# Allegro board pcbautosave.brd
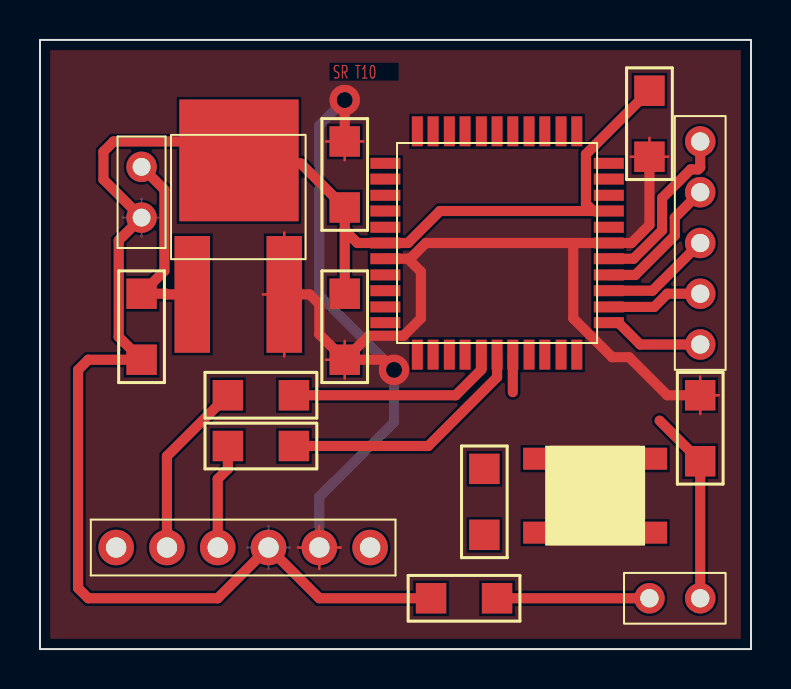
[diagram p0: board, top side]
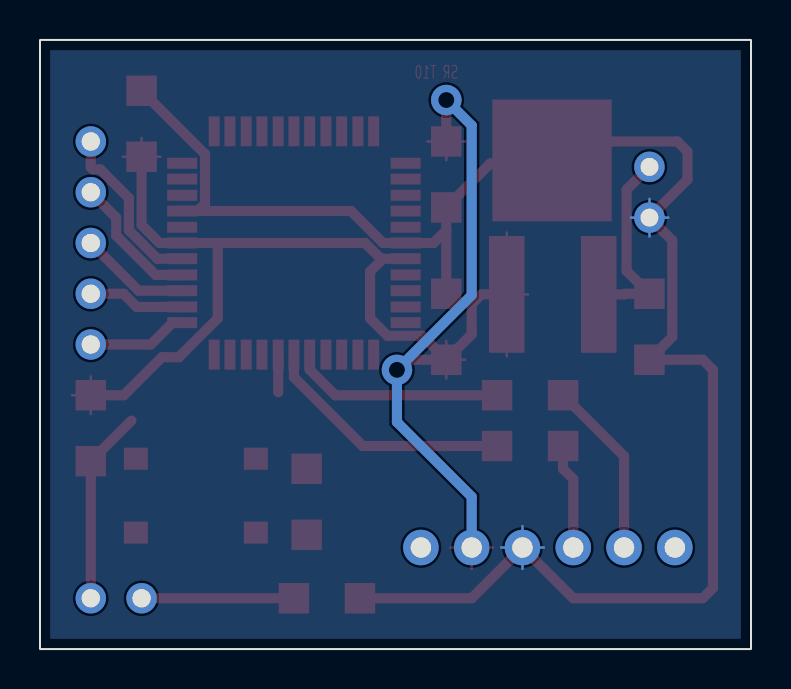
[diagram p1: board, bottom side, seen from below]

Outline 35.56 x 30.48 mm; copper layers: TOP, BOTTOM. Coordinates in mm from the lower left corner of the outline.
Outline path: rectangle 0,0 35.56,30.48

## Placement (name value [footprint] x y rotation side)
BT1  7.2V  [HEADER2]  5.08 22.86 0 top
C1  0.1uF, 15V  [SMC1206]  5.08 17.78 270 top
C2  0.1uF, 15V  [SMC1206]  15.24 25.4 270 top
C3  0.1uF, 15V  [SMC1206]  30.48 27.94 270 top
C4  0.1 uF, 15V  [SMC1206]  22.86 2.54 180 top
C5  0.1uF, 15V  [SMC1206]  15.24 17.78 270 top
J1  JUMPER  [JUMPER2]  30.48 2.54 0 top
J2  CON6  [HEADER6]  10.16 5.08 270 top
J3  HEADER 5  [JUMPER5]  33.02 15.24 90 top
R1  10 kohm, 1/4W  [SMR1206]  33.02 12.7 270 top
R2  220 ohm, 1/4W  [SMR1206]  22.22 5.72 90 top
R3  22 ohm, 1/4W  [SMR1206]  12.7 12.7 180 top
R4  22 ohm, 1/4W  [SMR1206]  12.7 10.16 180 top
SW1  SW PUSHBUTTON-SPST-2  [SMDSWITCH]  24.76 9.53 0 top
U1  LD29150DT33R  [TO252AA]  7.62 17.78 0 top
U2  PIC18F47K40-I/PT  [TQFPPIC18F47K40]  22.86 20.32 0 top

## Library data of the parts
BT1 = BATTERY
C1-C5 = CAP NP
J1 = JUMPER: User Part Number: ***
J2 = CON6
J3 = HEADER 5: User Part Number: ***
R1-R4 = R
SW1 = SW PUSHBUTTON-SPST-2
U1 = LD29150DT33R
U2 = PIC18F47K40-I/PT_2

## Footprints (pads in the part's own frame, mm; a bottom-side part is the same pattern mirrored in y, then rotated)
HEADER2
  round 1.524 hole 0.889: 1(0,1.27) 2(0,-1.27)
HEADER6
  round 1.778 hole 1.016: 1(0,6.35) 2(0,3.81) 3(0,1.27) 4(0,-1.27) 5(0,-3.81) 6(0,-6.35)
JUMPER2
  round 1.524 hole 0.914: 1(0,0) 2(2.54,0)
JUMPER5
  round 1.524 hole 0.914: 1(0,0) 2(2.54,0) 3(5.08,0) 4(7.62,0) 5(10.16,0)
SMC1206
  rect 1.524x1.524 smd: 1(0,0) 2(3.302,0)
SMDSWITCH
  rect 1.2x1.1 smd: 1(0,0) 2(6,0) 3(0,-3.7) 4(6,-3.7)
SMR1206
  rect 1.524x1.524 smd: 1(0,0) 2(3.302,0)
TO252AA
  rect 1.778x5.842 smd: 1(-0.004,-0.034) 3(4.596,-0.034)
  rect 5.969x6.096 smd: 2(2.332,6.673)
TQFPPIC18F47K40
  rect 1.5x0.55 smd: 1(-5.588,3.988) 2(-5.588,3.2) 3(-5.588,2.388) 4(-5.588,1.6) 5(-5.588,0.787) 6(-5.588,0) 7(-5.588,-0.787) 8(-5.588,-1.6) 9(-5.588,-2.388) 10(-5.588,-3.2) 11(-5.588,-3.988) 23(5.588,-3.988) 24(5.588,-3.2) 25(5.588,-2.388) 26(5.588,-1.6) 27(5.588,-0.787) 28(5.588,0) 29(5.588,0.787) 30(5.588,1.6) 31(5.588,2.388) 32(5.588,3.2) 33(5.588,3.988)
  rect 0.55x1.5 smd: 12(-3.988,-5.588) 13(-3.2,-5.588) 14(-2.388,-5.588) 15(-1.6,-5.588) 16(-0.787,-5.588) 17(0,-5.588) 18(0.787,-5.588) 19(1.6,-5.588) 20(2.388,-5.588) 21(3.2,-5.588) 22(3.988,-5.588) 34(3.988,5.588) 35(3.2,5.588) 36(2.388,5.588) 37(1.6,5.588) 38(0.787,5.588) 39(0,5.588) 40(-0.787,5.588) 41(-1.6,5.588) 42(-2.388,5.588) 43(-3.2,5.588) 44(-3.988,5.588)

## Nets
3.3V: C2.1 C3.2 C5.2 J2.2 R1.1 U1.3(OUT) U2.7(VDD_0) U2.28(VDD_1)
GND: BT1.2(-) C1.2 C2.2 C3.1 C4.2 C5.1 J2.3 SW1.3 U1.2(GND) U2.6(VSS_0) U2.30(VSS_1)
ICSPCLK: R3.1 U2.16(ICSPCLK/RB6)
ICSPDAT: R4.1 U2.17(ICSPDAT/RB7)
MCLR/VPP: J2.1 R2.1 U2.18(VPP/MCLR/RE3)
N103726: BT1.1(+) C1.1 U1.1(IN)
N112049: J2.4 R4.2
N112053: J2.5 R3.2
N112388: J1.2 R1.2 R2.2 SW1.1
N112486: C4.1 J1.1
N115043: J3.1 U2.23(RA4)
N115055: J3.2 U2.24(RA5)
N115065: J3.3 U2.25(RE0)
N115078: J3.4 U2.26(RE1)
N115090: J3.5 U2.27(RE2)

Pads without a net: J2 6; SW1 2 4; U2 1 2 3 4 5 8 9 10 11 12 13 14 15 19 20 21 22 29 31 32 33 34 35 36 37 38 39 40 41 42 43 44

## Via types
v1: diameter 1.524, hole 0.8, TOP to BOTTOM, 2 vias

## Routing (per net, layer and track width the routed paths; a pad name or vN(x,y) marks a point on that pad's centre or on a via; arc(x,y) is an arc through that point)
3.3V: length 95.8
  TOP w0.127: C3.2 31.42,24.64 ; C3.2 29.54,24.64 ; C3.2 30.48,25.58 ; 33.02,11.76 R1.1 ; R1.1 33.02,13.64 ; R1.1 33.96,12.7 ; 15.24,24.46 C2.1 ; C2.1 16.18,25.4 ; C2.1 14.3,25.4 ; 13.97,4.01 J2.2 ; J2.2 15.04,5.08 ; J2.2 13.97,6.15 ; J2.2 12.9,5.08 ; C5.2 15.24,15.42 ; C5.2 15.24,13.54 ; C5.2 14.3,14.48 ; 11.15,17.75 U1.3 ; U1.3 12.22,20.85 ; U1.3 12.22,14.65
  TOP w0.508: C2.1 v1(15.24,27.47) ; R1.1 31.37,12.7 29.46,14.6 28.61,14.6 26.67,16.55 26.67,20.32 ; U1.3 13.49,17.75 13.97,17.26 13.97,15.75 C5.2 ; 18.4,19.53 19.05,18.89 19.05,16.55 18.18,15.68 16.44,15.68 C5.2 ; 18.4,19.53 U2.7 ; 18.4,19.53 18.51,19.53 19.3,20.32 26.67,20.32 ; C5.2 17.2,14.48 v1(17.71,13.97) ; 26.67,20.32 U2.28 29.58,20.32 30.48,21.22 C3.2
  BOTTOM w0.508: v1(15.24,27.47) 13.97,26.2 13.97,17.71 v1(17.71,13.97) 17.71,11.36 13.97,7.62 J2.2
GND: length 94.3
  TOP w0.508: C5.1 15.24,20.95 ; 15.24,20.95 C2.2 13.04,24.3 10.1,24.3 U1.2 9.95,24.89 9.44,25.4 3.68,25.4 3.17,24.89 3.17,23.5 BT1.2 3.94,20.45 3.94,15.62 C1.2 2.41,14.48 1.91,13.97 1.91,3.05 2.41,2.54 8.89,2.54 J2.3 13.97,2.54 C4.2 ; 15.24,20.95 15.88,20.32 U2.6 18.4,20.32 20,21.92 27.67,21.92 ; 27.67,21.92 27.31,22.29 27.31,24.76 C3.1 ; 27.67,21.92 U2.30
  BOTTOM w0.127: J2.3 11.43,6.15 ; J2.3 12.5,5.08 ; J2.3 10.36,5.08 ; J2.3 11.43,4.01 ; BT1.2 6.02,21.59 ; BT1.2 5.08,22.53 ; BT1.2 4.14,21.59 ; BT1.2 5.08,20.65
ICSPCLK: length 10.7
  TOP w0.508: R3.1 20.79,12.7 22.07,13.98 U2.16
ICSPDAT: length 12.7
  TOP w0.508: U2.17 22.86,13.6 19.42,10.16 R4.1
MCLR/VPP: length 1.9
  TOP w0.508: 23.65,12.85 U2.18
N103726: length 9.8
  TOP w0.508: U1.1 6.35,17.75 6.31,17.78 C1.1 6.22,18.92 6.22,22.99 BT1.1
N112049: length 5.3
  TOP w0.508: J2.4 8.89,8.51 9.4,9.02 R4.2
N112053: length 8.9
  TOP w0.508: J2.5 6.35,9.65 R3.2
N112388: length 9.7
  TOP w0.508: 30.99,11.43 R1.2 J1.2
N112486: length 7.6
  TOP w0.508: C4.1 J1.1
N115043: length 5
  TOP w0.508: J3.1 30.02,15.24 28.92,16.33 U2.23
N115055: length 4.8
  TOP w0.508: J3.2 31.38,17.78 30.72,17.12 U2.24
N115065: length 5.6
  TOP w0.508: U2.25 30.63,17.93 J3.3
N115078: length 6.8
  TOP w0.508: U2.26 29.78,18.72 31.75,20.69 31.75,21.59 J3.4
N115090: length 8.7
  TOP w0.508: J3.5 33.02,24.1 32.92,24 32.55,24 31.11,22.57 31.11,20.96 29.69,19.53 U2.27

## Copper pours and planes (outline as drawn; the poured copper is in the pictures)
3.3V on TOP: 0.51,0.51 0.51,29.97 35.05,29.97 35.05,0.51
GND on BOTTOM: 0.51,0.51 0.51,29.97 35.05,29.97 35.05,0.51

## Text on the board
TOP: SR T10
